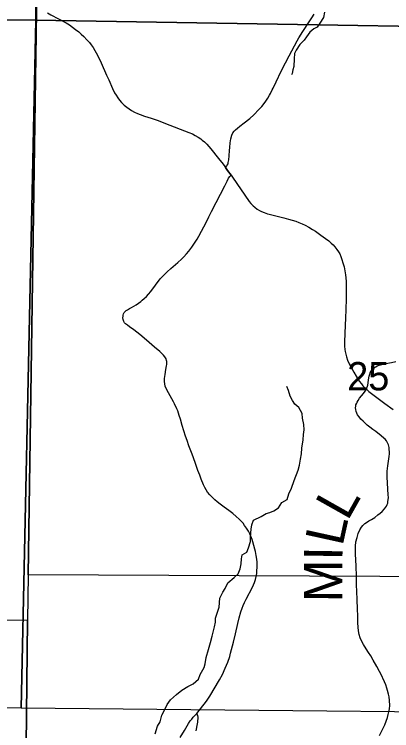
# Model space of a CAD drawing. Extents: x -19.9 to 41.9, y 0 to 32.3.
# Drawn here: x 4.967 to 5.525, y 14.677 to 15.736 of the extents above; entities that cross this region are included whole.
import ezdxf

# ---------------------------------------------------------------- set-up
doc = ezdxf.new("R2010")
doc.units = 0
for name, color, linetype in [('GM_X_Corporation', 7, 'Continuous'), ('GM_X_County_Road', 7, 'Continuous'), ('GM_X_Minor_River', 7, 'Continuous'), ('GM_X_Section', 7, 'Continuous'), ('GM_X_Section_Text', 7, 'Continuous'), ('GM_X_Township_Road', 7, 'Continuous'), ('GM_X_Township_Road_Text', 7, 'Continuous')]:
    doc.layers.add(name, color=color, linetype=linetype)

msp = doc.modelspace()

# ---------------------------------------------------------------- linework, layer by layer
at = {"layer": 'GM_X_Corporation'}
for points in [[(5.8404, 15.9209), (5.8188, 14.9036), (4.9872, 14.9075), (5.0009, 15.8404), (5.0026, 15.928)], [(3.9969, 15.8607), (5.0009, 15.8404), (4.9872, 14.9075), (4.9863, 14.8396), (3.9837, 14.8466)], [(4.9783, 14.1), (5.7974, 14.1), (5.8188, 14.9036), (4.9872, 14.9075), (4.9863, 14.8396)], [(3.9655, 14.1), (4.9783, 14.1), (4.9863, 14.8396), (3.9837, 14.8466)]]:
    msp.add_lwpolyline(points, close=True, dxfattribs=at)
at = {"layer": 'GM_X_County_Road'}
for points in [[(5.0155, 15.7383), (5.0207, 15.7353), (5.0431, 15.7231), (5.048, 15.7202), (5.0526, 15.7171), (5.0573, 15.7137), (5.0621, 15.7098), (5.0655, 15.7068), (5.0694, 15.703), (5.0739, 15.6983), (5.0776, 15.6941), (5.0802, 15.6909), (5.083, 15.6869), (5.0857, 15.6826), (5.0875, 15.679), (5.0926, 15.6695), (5.095, 15.6641), (5.1031, 15.6458), (5.1062, 15.6389), (5.1116, 15.6263), (5.1149, 15.62), (5.1172, 15.6162), (5.1197, 15.6123), (5.1224, 15.6088), (5.1253, 15.6057), (5.1291, 15.6018), (5.1329, 15.5988), (5.1365, 15.596), (5.1398, 15.5939), (5.1441, 15.5914), (5.1486, 15.5893), (5.1527, 15.5877), (5.1592, 15.5854), (5.1688, 15.5822), (5.1791, 15.5788), (5.19, 15.5745), (5.2246, 15.5613), (5.23, 15.559), (5.2342, 15.5569), (5.2384, 15.5545), (5.2422, 15.5519), (5.2446, 15.5501), (5.2476, 15.5474), (5.2513, 15.5438), (5.2543, 15.5405), (5.2572, 15.5372), (5.2686, 15.523), (5.2752, 15.5142), (5.2778, 15.5107), (5.2787, 15.5095)], [(5.2787, 15.5095), (5.282, 15.5051), (5.2871, 15.4982)], [(5.2871, 15.4982), (5.2894, 15.4952), (5.3141, 15.4594), (5.3165, 15.4562), (5.3196, 15.453), (5.322, 15.4508), (5.3256, 15.448), (5.329, 15.4461), (5.3319, 15.4445), (5.3358, 15.4429), (5.3408, 15.4412), (5.3434, 15.4405), (5.365, 15.435), (5.3722, 15.4332), (5.3774, 15.4318), (5.383, 15.43), (5.3875, 15.4283), (5.392, 15.4264), (5.3968, 15.4241), (5.4019, 15.4214), (5.4073, 15.418), (5.4118, 15.4152), (5.42, 15.4092), (5.4268, 15.4044), (5.4315, 15.401), (5.4353, 15.3978), (5.4381, 15.3951), (5.4407, 15.392), (5.4435, 15.3884), (5.4459, 15.385), (5.4478, 15.3817), (5.4495, 15.3777), (5.451, 15.3737), (5.4525, 15.3687), (5.4542, 15.3628), (5.4553, 15.3567), (5.4562, 15.3506), (5.4571, 15.3412), (5.4574, 15.3258), (5.4572, 15.3158), (5.457, 15.2993), (5.4565, 15.2872), (5.4552, 15.2644), (5.4548, 15.2515), (5.4549, 15.2453), (5.4553, 15.2406), (5.4558, 15.2373), (5.4566, 15.2334), (5.4576, 15.2294), (5.4593, 15.2249), (5.4617, 15.2193), (5.465, 15.2133), (5.4687, 15.2068), (5.472, 15.2011), (5.4767, 15.1936), (5.4797, 15.1895), (5.4819, 15.1867), (5.4847, 15.184), (5.4871, 15.1817), (5.4887, 15.1803), (5.4909, 15.1785), (5.5146, 15.1607), (5.5269, 15.1516)]]:
    msp.add_lwpolyline(points, dxfattribs=at)
at = {"layer": 'GM_X_Minor_River'}
for points in [[(5.4254, 15.7393), (5.424, 15.7313), (5.4185, 15.7229), (5.4144, 15.7171), (5.4095, 15.7143), (5.4035, 15.7093), (5.3987, 15.7028), (5.3954, 15.6978), (5.389, 15.6912), (5.3835, 15.6831), (5.3809, 15.6778), (5.3803, 15.6701), (5.3797, 15.6587), (5.3786, 15.6537), (5.3772, 15.6484), (5.3763, 15.6466)], [(5.3446, 14.9997), (5.3502, 15.0021), (5.3574, 15.0064), (5.3622, 15.0144), (5.3701, 15.0187), (5.3726, 15.0272), (5.3766, 15.0356), (5.3806, 15.0467), (5.3865, 15.062), (5.3882, 15.0696), (5.3896, 15.0784), (5.391, 15.086), (5.3917, 15.0948), (5.3938, 15.107), (5.394, 15.115), (5.3951, 15.1215), (5.3946, 15.1295), (5.3929, 15.139), (5.3921, 15.1458), (5.3874, 15.1545), (5.3813, 15.1594), (5.3778, 15.165), (5.3746, 15.1714), (5.3719, 15.1798), (5.3694, 15.1859)], [(5.1748, 14.6722), (5.1785, 14.6836), (5.1825, 14.6898), (5.1847, 14.6997), (5.1884, 14.7062), (5.1928, 14.7158), (5.1976, 14.7224), (5.2065, 14.7305), (5.2144, 14.7367), (5.223, 14.7425), (5.2313, 14.7461), (5.2388, 14.753), (5.2413, 14.7599), (5.2472, 14.7703), (5.249, 14.776), (5.2504, 14.7852), (5.2537, 14.797), (5.2565, 14.8074), (5.2591, 14.8165), (5.2612, 14.8246), (5.2626, 14.8307), (5.264, 14.8375), (5.2643, 14.8432), (5.2694, 14.8593), (5.2703, 14.8726), (5.2748, 14.8815), (5.2785, 14.8872), (5.2821, 14.8953), (5.2915, 14.9034), (5.2978, 14.9088), (5.3004, 14.9161), (5.3022, 14.9234), (5.3024, 14.931), (5.3035, 14.9371), (5.3102, 14.941), (5.3128, 14.9471), (5.3157, 14.9567), (5.3156, 14.9635), (5.3166, 14.9746), (5.318, 14.9811), (5.3202, 14.9879), (5.3318, 14.9934), (5.3389, 14.9981), (5.3446, 14.9997)]]:
    msp.add_lwpolyline(points, dxfattribs=at)
at = {"layer": 'GM_X_Section'}
for points in [[(4.1751, 16.7729), (5.0099, 16.7619), (4.9984, 15.7274), (4.1607, 15.7345), (4.1739, 16.6474)], [(5.0099, 16.7619), (6.0276, 16.7357), (6.0103, 15.7106), (4.9984, 15.7274)], [(4.9984, 15.7274), (4.9768, 14.7102), (4.1452, 14.714), (4.1589, 15.6469), (4.1607, 15.7345)], [(6.0103, 15.7106), (5.9806, 14.7005), (4.9768, 14.7102), (4.9984, 15.7274)]]:
    msp.add_lwpolyline(points, close=True, dxfattribs=at)
at = {"layer": 'GM_X_Township_Road'}
for points in [[(5.348, 15.6241), (5.3493, 15.6267), (5.3538, 15.6359), (5.3613, 15.6517), (5.3675, 15.6644), (5.373, 15.6743), (5.385, 15.6965), (5.3875, 15.7009), (5.3933, 15.7105), (5.3962, 15.715), (5.4007, 15.7216), (5.4067, 15.7305), (5.4098, 15.736)], [(5.2787, 15.5095), (5.2808, 15.5117), (5.2815, 15.5128), (5.2826, 15.5149), (5.283, 15.5169), (5.2837, 15.5206), (5.2841, 15.5267), (5.2848, 15.5346), (5.2853, 15.539), (5.286, 15.546), (5.2868, 15.552), (5.288, 15.5571), (5.2898, 15.5607), (5.2918, 15.5633), (5.2939, 15.5651), (5.2966, 15.5677), (5.3002, 15.5706), (5.3064, 15.5755), (5.3147, 15.5819), (5.321, 15.5875), (5.3282, 15.5951), (5.3305, 15.5976), (5.3324, 15.5997), (5.3359, 15.6041), (5.3384, 15.6075), (5.3414, 15.6121), (5.3439, 15.6162), (5.3453, 15.6188), (5.348, 15.6241)], [(5.2871, 15.4982), (5.282, 15.5051), (5.2787, 15.5095)], [(5.2365, 14.7022), (5.2509, 14.7206), (5.2529, 14.7234), (5.2556, 14.7278), (5.2699, 14.7523), (5.2743, 14.7601), (5.2786, 14.7693), (5.2822, 14.778), (5.2851, 14.7865), (5.2865, 14.7915), (5.2879, 14.7968), (5.2892, 14.8023), (5.2905, 14.8078), (5.2935, 14.8203), (5.297, 14.8355), (5.299, 14.8439), (5.3015, 14.8526), (5.3034, 14.8581), (5.3051, 14.8622), (5.3071, 14.8665), (5.3094, 14.8712), (5.3188, 14.889), (5.3217, 14.896), (5.3232, 14.9006), (5.3242, 14.9051), (5.325, 14.9092), (5.3254, 14.9133), (5.3256, 14.9185), (5.3255, 14.9262), (5.3251, 14.9305), (5.3243, 14.936), (5.3232, 14.9419), (5.3224, 14.9453), (5.3193, 14.9563), (5.3181, 14.9598), (5.3163, 14.9647), (5.3149, 14.9679), (5.3127, 14.9721), (5.3101, 14.9764), (5.3072, 14.9805), (5.3049, 14.9835), (5.3019, 14.9868), (5.299, 14.9897), (5.2944, 14.9938), (5.2896, 14.9978), (5.2836, 15.0025), (5.2768, 15.0074), (5.2708, 15.0117), (5.2667, 15.0152), (5.2633, 15.0183), (5.26, 15.0214), (5.2559, 15.0255), (5.2525, 15.0294), (5.2501, 15.033), (5.2481, 15.0364), (5.2462, 15.0402), (5.2429, 15.0487), (5.2409, 15.0545), (5.2382, 15.0615), (5.2346, 15.0719), (5.2315, 15.0802), (5.2294, 15.0857), (5.2249, 15.0978), (5.2221, 15.1058), (5.2199, 15.1123), (5.2173, 15.1202), (5.2148, 15.1283), (5.2122, 15.1374), (5.2104, 15.1429), (5.2082, 15.1499), (5.2071, 15.1526), (5.2037, 15.1599), (5.202, 15.1633), (5.1973, 15.1719), (5.1946, 15.1763), (5.192, 15.1808), (5.1898, 15.1862), (5.189, 15.1897), (5.1886, 15.1932), (5.1888, 15.1975), (5.1895, 15.2035), (5.1908, 15.211), (5.1918, 15.2164), (5.192, 15.2185), (5.1919, 15.2228), (5.1917, 15.2242), (5.191, 15.2264), (5.1902, 15.2281), (5.189, 15.2298), (5.1874, 15.232), (5.1853, 15.2342), (5.1817, 15.2374), (5.174, 15.244), (5.1619, 15.2544), (5.152, 15.2626), (5.1434, 15.2693), (5.137, 15.2737), (5.1338, 15.2763), (5.1311, 15.2785), (5.1297, 15.28), (5.1287, 15.2816), (5.128, 15.2833), (5.1276, 15.285), (5.1273, 15.2874), (5.1275, 15.2896), (5.1276, 15.2911), (5.1282, 15.2932), (5.1292, 15.2952), (5.1304, 15.2966), (5.1321, 15.298), (5.1341, 15.2993), (5.1367, 15.301), (5.1398, 15.3025), (5.1469, 15.3067), (5.1536, 15.3116), (5.1557, 15.3132), (5.1587, 15.3158), (5.1619, 15.3188), (5.165, 15.3221), (5.1684, 15.3261), (5.1825, 15.3449), (5.1873, 15.3499), (5.1927, 15.3554), (5.1982, 15.3601), (5.2084, 15.3689), (5.2139, 15.3741), (5.2175, 15.3776), (5.2214, 15.3818), (5.2245, 15.3856), (5.2291, 15.3919), (5.2368, 15.4036), (5.2396, 15.408), (5.2435, 15.4153), (5.2501, 15.4281), (5.2544, 15.4367), (5.2583, 15.4442), (5.2653, 15.4577), (5.2778, 15.4823), (5.2812, 15.4895), (5.2834, 15.4936), (5.2853, 15.4961), (5.2871, 15.4982)], [(5.4871, 15.1817), (5.4876, 15.1828), (5.4885, 15.1849), (5.4892, 15.1877), (5.4897, 15.1912), (5.4903, 15.1956), (5.4913, 15.201), (5.4921, 15.204), (5.4929, 15.2061), (5.4941, 15.2086), (5.4959, 15.2108), (5.4972, 15.2122), (5.4992, 15.2139), (5.5009, 15.215), (5.5032, 15.2162), (5.5063, 15.2174), (5.5102, 15.2185), (5.5158, 15.2196), (5.5242, 15.2212), (5.5307, 15.2228)], [(5.5068, 14.6698), (5.5114, 14.6796), (5.5142, 14.6857), (5.5162, 14.6908), (5.5185, 14.6966), (5.5196, 14.7007), (5.5205, 14.705), (5.5212, 14.7092), (5.5216, 14.714), (5.5214, 14.7217), (5.5207, 14.7268), (5.5199, 14.7311), (5.5186, 14.7363), (5.5175, 14.74), (5.5157, 14.7448), (5.5139, 14.7493), (5.5085, 14.7608), (5.5067, 14.7645), (5.5028, 14.772), (5.4974, 14.7814), (5.4937, 14.7875), (5.4905, 14.7926), (5.4869, 14.798), (5.4831, 14.8043), (5.4801, 14.8097), (5.478, 14.8141), (5.4763, 14.819), (5.4753, 14.8244), (5.4748, 14.83), (5.4745, 14.8362), (5.4744, 14.8431), (5.4741, 14.8598), (5.4737, 14.8676), (5.4734, 14.8734), (5.4728, 14.8802), (5.4726, 14.8949), (5.4725, 14.9054), (5.4721, 14.92), (5.4712, 14.9383), (5.471, 14.9498), (5.4717, 14.956), (5.4734, 14.9626), (5.4751, 14.9683), (5.4777, 14.974), (5.4798, 14.9777), (5.4821, 14.9803), (5.4851, 14.9831), (5.4886, 14.9855), (5.491, 14.987), (5.4949, 14.9893), (5.4995, 14.9923), (5.5043, 14.9958), (5.5073, 14.9983), (5.5104, 15.0009), (5.5141, 15.005), (5.5168, 15.0086), (5.518, 15.0113), (5.5188, 15.0135), (5.5191, 15.0158), (5.5194, 15.0183), (5.5197, 15.0217), (5.5196, 15.0256), (5.5182, 15.0428), (5.5178, 15.0521), (5.5179, 15.0608), (5.519, 15.0684), (5.52, 15.0752), (5.5209, 15.0822), (5.5211, 15.0863), (5.5207, 15.0954), (5.5197, 15.0995), (5.518, 15.1035), (5.5169, 15.1054), (5.5148, 15.1077), (5.5128, 15.1096), (5.5088, 15.1128), (5.501, 15.119), (5.4968, 15.122), (5.4923, 15.1256), (5.4885, 15.1287), (5.4852, 15.1317), (5.4822, 15.1344), (5.4791, 15.1376), (5.4763, 15.141), (5.4742, 15.1439), (5.4728, 15.1465), (5.4719, 15.149), (5.4714, 15.1519), (5.4713, 15.154), (5.4714, 15.1566), (5.4718, 15.1586), (5.4728, 15.1613), (5.4735, 15.1628), (5.4749, 15.1651), (5.4772, 15.1684), (5.4827, 15.1754), (5.4852, 15.1789), (5.4871, 15.1817)], [(5.2119, 14.6668), (5.2182, 14.6773), (5.2243, 14.6874), (5.2267, 14.6914), (5.2289, 14.6941), (5.2313, 14.6968), (5.2332, 14.6987), (5.2365, 14.7022)], [(5.2353, 14.6769), (5.2375, 14.6872), (5.2379, 14.6897), (5.2382, 14.6922), (5.2385, 14.6946), (5.2386, 14.6968), (5.238, 14.6992), (5.2372, 14.7008), (5.2365, 14.7022)]]:
    msp.add_lwpolyline(points, dxfattribs=at)

# ---------------------------------------------------------------- texts
at = {"layer": 'GM_X_Section_Text'}
msp.add_text('25', height=0.04186, rotation=0, dxfattribs=at).set_placement((5.4588, 15.18))
at = {"layer": 'GM_X_Township_Road_Text'}
for s, rotation, p in [('L', 60.6394, (5.4592, 14.9857)), ('L', 77.626, (5.4517, 14.9483)), ('I', 89.1647, (5.4517, 14.928)), ('M', 89.9675, (5.4517, 14.8666))]:
    msp.add_text(s, height=0.0568, rotation=rotation, dxfattribs=at).set_placement(p)

doc.saveas('drawing.dxf')
